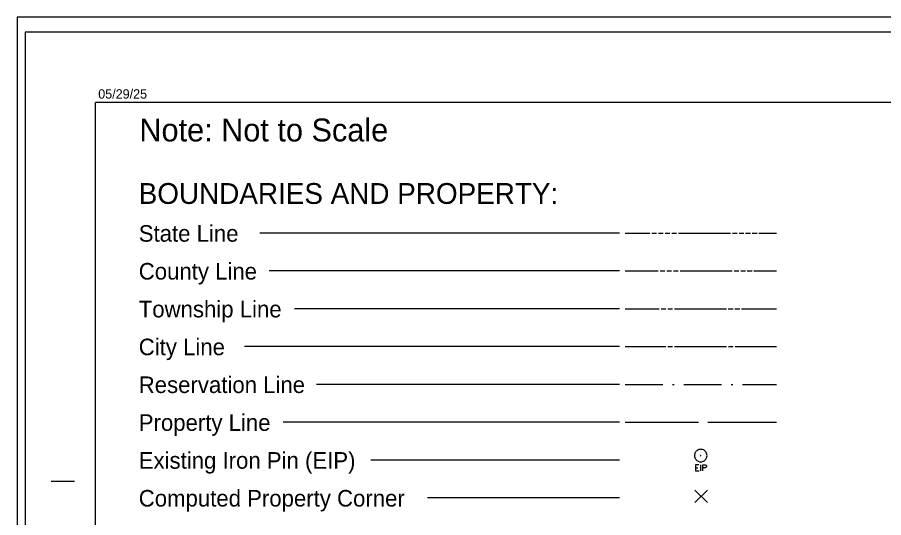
# Model space of a CAD drawing. Extents: x 811137 to 813186, y 647386 to 648494.
# Drawn here: x 811136.6 to 811598.2, y 648227.1 to 648494 of the extents above; entities that cross this region are included whole.
import ezdxf

# ---------------------------------------------------------------- set-up
doc = ezdxf.new("R2010")
doc.units = 0
for name, color, linetype in [('Default', 7, 'Continuous'), ('Sheet_Plan', 7, 'Continuous'), ('Sheet_Symbology', 7, 'Continuous'), ('z - Construction', 7, 'Continuous')]:
    doc.layers.add(name, color=color, linetype=linetype)

msp = doc.modelspace()

# ---------------------------------------------------------------- linework, layer by layer
at = {"layer": 'Default'}
msp.add_line((811154.58, 648246.52), (811167.08, 648246.52), dxfattribs=at)
msp.add_lwpolyline([(812820.63, 648494.02), (811136.63, 648494.02), (811136.63, 647394.02), (812820.63, 647394.02)], close=True, dxfattribs=at)
at = {"layer": 'Sheet_Plan'}
for p, q in [((811208.24, 648456.11), (811208.24, 648456.11)), ((811178.28, 647423.58), (811178.27, 648448.58)), ((812803.27, 648448.58), (811178.27, 648448.58))]:
    msp.add_line(p, q, dxfattribs=at)
at = {"layer": 'Sheet_Symbology'}
for p, q in [((811457.46, 648378.91), (811265.77, 648378.91)), ((811460.36, 648378.91), (811473.67, 648378.91)), ((811474.68, 648378.91), (811477.21, 648378.91)), ((811478.21, 648378.91), (811480.74, 648378.91)), ((811481.75, 648378.91), (811484.27, 648378.91)), ((811485.28, 648378.91), (811487.8, 648378.91)), ((811488.81, 648378.91), (811516.55, 648378.91)), ((811517.56, 648378.91), (811520.09, 648378.91)), ((811521.09, 648378.91), (811523.62, 648378.91)), ((811524.63, 648378.91), (811527.15, 648378.91)), ((811528.16, 648378.91), (811530.68, 648378.91)), ((811531.69, 648378.91), (811541.07, 648378.91)), ((811457.46, 648358.73), (811270.8, 648358.73)), ((811460.36, 648358.73), (811478.1, 648358.73)), ((811479.11, 648358.73), (811481.63, 648358.73)), ((811482.64, 648358.73), (811485.16, 648358.73)), ((811486.17, 648358.73), (811488.7, 648358.73)), ((811489.7, 648358.73), (811517.45, 648358.73)), ((811518.46, 648358.73), (811520.98, 648358.73)), ((811521.99, 648358.73), (811524.51, 648358.73)), ((811525.52, 648358.73), (811528.04, 648358.73)), ((811529.05, 648358.73), (811541.07, 648358.73)), ((811457.46, 648338.55), (811284.22, 648338.55)), ((811460.36, 648338.55), (811478.57, 648338.55)), ((811479.58, 648338.55), (811482.1, 648338.55)), ((811483.11, 648338.55), (811485.63, 648338.55)), ((811486.64, 648338.55), (811514.39, 648338.55)), ((811515.39, 648338.55), (811517.92, 648338.55)), ((811518.93, 648338.55), (811521.45, 648338.55)), ((811522.46, 648338.55), (811541.07, 648338.55)), ((811457.46, 648318.37), (811257.62, 648318.37)), ((811460.36, 648318.37), (811482.19, 648318.37)), ((811483.2, 648318.37), (811485.72, 648318.37)), ((811486.73, 648318.37), (811514.47, 648318.37)), ((811515.48, 648318.37), (811518, 648318.37)), ((811519.01, 648318.37), (811541.07, 648318.37)), ((811457.46, 648298.2), (811295.95, 648298.2)), ((811460.36, 648298.2), (811480.54, 648298.2)), ((811485.58, 648298.2), (811486.59, 648298.2)), ((811491.63, 648298.2), (811511.81, 648298.2)), ((811516.86, 648298.2), (811517.87, 648298.2)), ((811522.91, 648298.2), (811541.07, 648298.2)), ((811457.46, 648278.02), (811278.2, 648278.02)), ((811460.36, 648278.02), (811499.45, 648278.02)), ((811504.5, 648278.02), (811541.07, 648278.02)), ((811457.46, 648257.84), (811325, 648257.84)), ((811497.83, 648253.66), (811499.15, 648253.66)), ((811500.72, 648252.04), (811500.72, 648255.26)), ((811457.46, 648237.66), (811355.11, 648237.66)), ((811504.26, 648235.22), (811497.59, 648241.89)), ((811497.59, 648235.22), (811504.26, 648241.89))]:
    msp.add_line(p, q, dxfattribs=at)
for points in [[(811504.04, 648260.26), (811504.01, 648260.69), (811503.93, 648261.09), (811503.8, 648261.49), (811503.64, 648261.87), (811503.4, 648262.22), (811503.13, 648262.54), (811502.83, 648262.83), (811502.48, 648263.07), (811502.14, 648263.29), (811501.73, 648263.42), (811501.33, 648263.53), (811500.93, 648263.58), (811500.5, 648263.58), (811500.07, 648263.53), (811499.67, 648263.42), (811499.29, 648263.29), (811498.92, 648263.07), (811498.57, 648262.83), (811498.27, 648262.54), (811498.01, 648262.22), (811497.79, 648261.87), (811497.6, 648261.49), (811497.47, 648261.09), (811497.39, 648260.69), (811497.36, 648260.26), (811497.39, 648259.83), (811497.47, 648259.43), (811497.6, 648259.03), (811497.79, 648258.65), (811498.01, 648258.3), (811498.27, 648257.98), (811498.57, 648257.68), (811498.92, 648257.44), (811499.29, 648257.23), (811499.67, 648257.1), (811500.07, 648256.99), (811500.5, 648256.93), (811500.93, 648256.93), (811501.33, 648256.99), (811501.73, 648257.1), (811502.14, 648257.23), (811502.48, 648257.44), (811502.83, 648257.68), (811503.13, 648257.98), (811503.4, 648258.3), (811503.64, 648258.65), (811503.8, 648259.03), (811503.93, 648259.43), (811504.01, 648259.83), (811504.04, 648260.26)], [(811500.77, 648260.34), (811500.69, 648260.37), (811500.63, 648260.31), (811500.61, 648260.23), (811500.66, 648260.18), (811500.74, 648260.15), (811500.79, 648260.21), (811500.82, 648260.29), (811500.77, 648260.34)], [(811499.68, 648255.26), (811497.83, 648255.26), (811497.83, 648252.04), (811499.81, 648252.04)], [(811501.79, 648252.04), (811501.79, 648255.26), (811503.09, 648255.26), (811503.47, 648255.14), (811503.8, 648254.63), (811503.8, 648254.32), (811503.5, 648253.82), (811503.09, 648253.69), (811501.79, 648253.69)]]:
    msp.add_lwpolyline(points, dxfattribs=at)
at = {"layer": 'z - Construction'}
for p, q in [((812840.77, 648486.08), (811140.78, 648486.08)), ((811140.78, 648486.08), (811140.78, 647386.08))]:
    msp.add_line(p, q, dxfattribs=at)

# ---------------------------------------------------------------- texts
at = {"layer": 'Sheet_Plan'}
msp.add_text('05/29/25', height=5, rotation=0, dxfattribs=at).set_placement((811179.73, 648450.65))
at = {"layer": 'Sheet_Symbology'}
msp.add_text('Note: Not to Scale', height=12.2158, rotation=360, dxfattribs=at).set_placement((811201.64, 648427.81))
for s, height, p in [('BOUNDARIES AND PROPERTY:', 11.0983, (811201.3, 648394.5)), ('State Line', 8.828, (811201.31, 648374.33)), ('County Line', 8.8282, (811201.31, 648354.15)), ('Township Line', 8.8282, (811201.31, 648333.97)), ('City Line', 8.828, (811201.31, 648313.8)), ('Reservation Line', 8.8282, (811201.31, 648293.62)), ('Property Line', 8.8282, (811201.31, 648273.44)), ('Existing Iron Pin (EIP)', 8.8282, (811201.31, 648253.26)), ('Computed Property Corner', 8.8282, (811201.31, 648233.08))]:
    msp.add_text(s, height=height, dxfattribs=at).set_placement(p)

doc.saveas('drawing.dxf')
